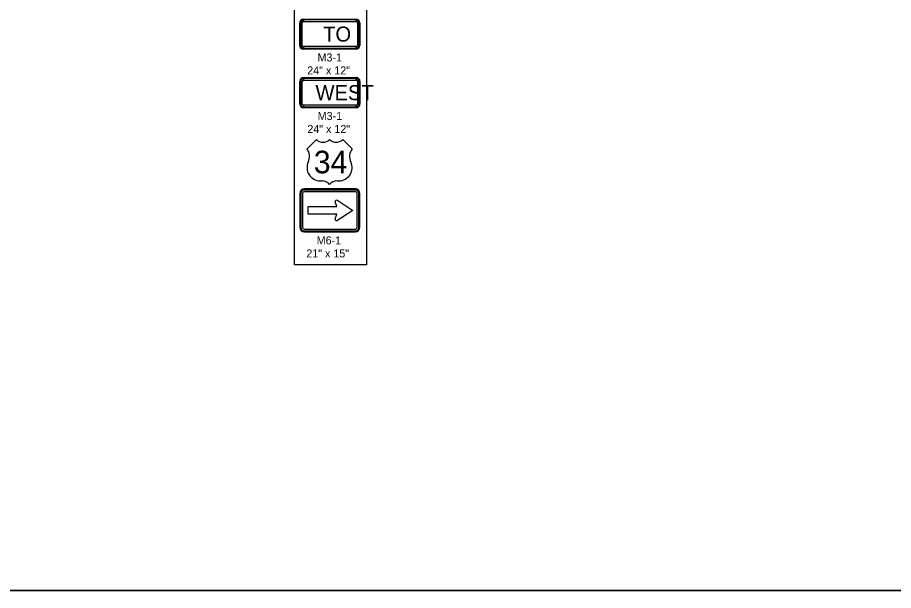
# Model space of a CAD drawing. Extents: x 10133 to 81668, y 6132 to 11018.
# Drawn here: x 11517 to 12392, y 7924 to 8497 of the extents above; entities that cross this region are included whole.
import ezdxf

# ---------------------------------------------------------------- set-up
doc = ezdxf.new("R2010")
doc.units = 0
for name, color, linetype in [('dsnTextFinalPlan', 7, 'Continuous'), ('Level 10', 7, 'Continuous'), ('Level 4', 7, 'Continuous'), ('Level 5', 7, 'Continuous'), ('SheetBorder', 7, 'Continuous'), ('SheetText', 7, 'Continuous')]:
    doc.layers.add(name, color=color, linetype=linetype)

msp = doc.modelspace()

# ---------------------------------------------------------------- linework, layer by layer
at = {"layer": 'dsnTextFinalPlan'}
msp.add_lwpolyline([(11793.9, 8561.72), (11865.97, 8561.72), (11865.97, 8249.49), (11793.9, 8249.49)], close=True, dxfattribs=at)
msp.add_lwpolyline([(11793.9, 8561.72), (11865.97, 8561.72), (11865.97, 8249.49), (11793.9, 8249.49)], close=True, dxfattribs=at)
at = {"layer": 'Level 10'}
for p, q in [((11799.19, 8468.76), (11799.19, 8491.3)), ((11800.13, 8491.3), (11801.69, 8491.3)), ((11802.95, 8495.06), (11855.56, 8495.06)), ((11802.95, 8492.56), (11802.95, 8494.12)), ((11855.56, 8494.12), (11855.56, 8492.56)), ((11856.81, 8491.3), (11858.38, 8491.3)), ((11859.32, 8491.3), (11859.32, 8468.76)), ((11801.69, 8468.76), (11800.13, 8468.76)), ((11802.95, 8465.94), (11802.95, 8467.5)), ((11855.56, 8465), (11802.95, 8465)), ((11855.56, 8467.5), (11855.56, 8465.94)), ((11858.38, 8468.76), (11856.81, 8468.76)), ((11803.05, 8436.52), (11855.66, 8436.52)), ((11799.29, 8410.21), (11799.29, 8432.76)), ((11800.23, 8432.76), (11801.8, 8432.76)), ((11803.05, 8434.01), (11803.05, 8435.58)), ((11855.66, 8435.58), (11855.66, 8434.01)), ((11856.92, 8432.76), (11858.48, 8432.76)), ((11859.42, 8432.76), (11859.42, 8410.21)), ((11801.8, 8410.21), (11800.23, 8410.21)), ((11858.48, 8410.21), (11856.92, 8410.21)), ((11803.05, 8407.39), (11803.05, 8408.96)), ((11855.66, 8406.45), (11803.05, 8406.45)), ((11855.66, 8408.96), (11855.66, 8407.39)), ((11854.79, 8325.33), (11803.83, 8325.33)), ((11854.79, 8324.18), (11803.83, 8324.18)), ((11854.79, 8322.47), (11803.83, 8322.47)), ((11799.25, 8320.75), (11799.25, 8286.96)), ((11800.39, 8320.75), (11800.39, 8286.96)), ((11802.11, 8320.75), (11802.11, 8286.96)), ((11856.51, 8286.96), (11856.51, 8320.75)), ((11858.23, 8286.96), (11858.23, 8320.75)), ((11859.37, 8286.96), (11859.37, 8320.75)), ((11803.83, 8285.24), (11854.79, 8285.24)), ((11803.83, 8283.53), (11854.79, 8283.53)), ((11803.83, 8282.38), (11854.79, 8282.38))]:
    msp.add_line(p, q, dxfattribs=at)
for points in [[(11800.13, 8491.3), (11800.13, 8468.76), (11801.69, 8468.76), (11801.69, 8491.3), (11800.13, 8491.3)], [(11855.56, 8494.12), (11802.95, 8494.12), (11802.95, 8492.56), (11855.56, 8492.56), (11855.56, 8494.12)], [(11858.38, 8468.76), (11858.38, 8491.3), (11856.81, 8491.3), (11856.81, 8468.76), (11858.38, 8468.76)], [(11802.95, 8465.94), (11855.56, 8465.94), (11855.56, 8467.5), (11802.95, 8467.5), (11802.95, 8465.94)], [(11800.23, 8432.76), (11800.23, 8410.21), (11801.8, 8410.21), (11801.8, 8432.76), (11800.23, 8432.76)], [(11855.66, 8435.58), (11803.05, 8435.58), (11803.05, 8434.01), (11855.66, 8434.01), (11855.66, 8435.58)], [(11858.48, 8410.21), (11858.48, 8432.76), (11856.92, 8432.76), (11856.92, 8410.21), (11858.48, 8410.21)], [(11803.05, 8407.39), (11855.66, 8407.39), (11855.66, 8408.96), (11803.05, 8408.96), (11803.05, 8407.39)]]:
    msp.add_lwpolyline(points, close=True, dxfattribs=at)
for points in [[(11837.23, 8313.67), (11852.22, 8303.86), (11837.23, 8294.07)], [(11834.76, 8295.4), (11836.13, 8299.98), (11807.6, 8299.98), (11807.6, 8307.73), (11836.13, 8307.73), (11834.73, 8312.31)]]:
    msp.add_lwpolyline(points, dxfattribs=at)
for centre, radius, start, end in [((11802.95, 8491.3), 3.76, 90, 180), ((11802.95, 8491.3), 2.82, 90.00021, 179.99985), ((11802.95, 8491.3), 1.25, 90.00021, 179.99985), ((11855.56, 8491.3), 3.76, 0, 90), ((11855.56, 8491.3), 2.82, 0, 90.00021), ((11855.56, 8491.3), 1.25, 0, 90.00021), ((11802.95, 8468.76), 3.76, 180, 270), ((11802.95, 8468.76), 2.82, 179.99985, 270.00006), ((11802.95, 8468.76), 1.25, 179.99985, 270.00006), ((11855.56, 8468.76), 2.82, 270.00006, 0.00027), ((11855.56, 8468.76), 1.25, 270.00006, 0.00027), ((11855.56, 8468.76), 3.76, 270, 359.99112), ((11803.05, 8432.76), 3.76, 90, 180), ((11855.66, 8432.76), 3.76, 0, 90), ((11803.05, 8432.76), 2.82, 90.00021, 179.99985), ((11803.05, 8432.76), 1.25, 90.00021, 179.99985), ((11855.66, 8432.76), 2.82, 0, 90.00021), ((11855.66, 8432.76), 1.25, 0, 90.00021), ((11803.05, 8410.21), 3.76, 180, 270), ((11803.05, 8410.21), 2.82, 179.99985, 270.00006), ((11803.05, 8410.21), 1.25, 179.99985, 270.00006), ((11855.66, 8410.21), 2.82, 270.00006, 0.00027), ((11855.66, 8410.21), 1.25, 270.00006, 0.00027), ((11855.66, 8410.21), 3.76, 270, 359.99112), ((11803.83, 8320.75), 4.58, 90, 180), ((11803.83, 8320.75), 3.44, 90, 180), ((11803.83, 8320.75), 1.72, 90, 180), ((11854.79, 8320.75), 4.58, 360, 90), ((11854.79, 8320.75), 3.44, 0, 90), ((11854.79, 8320.75), 1.72, 0, 90), ((11836.11, 8312.7), 1.43, 56.61094, 195.96908), ((11915.68, 8433.43), 143.16, 236.61094, 236.7714), ((11836.11, 8295.01), 1.4, 164.03092, 303.3104), ((11915.5, 8174.2), 143.16, 123.14303, 123.31039), ((11803.83, 8286.96), 4.58, 180, 270), ((11803.83, 8286.96), 3.44, 180, 270), ((11803.83, 8286.96), 1.72, 180, 270), ((11854.79, 8286.96), 4.58, 270, 0), ((11854.79, 8286.96), 3.44, 270, 360), ((11854.79, 8286.96), 1.72, 270, 0)]:
    msp.add_arc(centre, radius, start, end, dxfattribs=at)
at = {"layer": 'Level 4'}
for p, q in [((11815.89, 8374.68), (11806.51, 8365.31)), ((11815.89, 8374.68), (11806.51, 8365.31)), ((11851.51, 8365.31), (11842.14, 8374.68)), ((11851.51, 8365.31), (11842.14, 8374.68)), ((11819.64, 8333.43), (11821.51, 8333.43)), ((11819.64, 8333.43), (11821.51, 8333.43)), ((11836.51, 8333.43), (11838.39, 8333.43)), ((11836.51, 8333.43), (11838.39, 8333.43))]:
    msp.add_line(p, q, dxfattribs=at)
for centre, radius, start, end in [((11822.45, 8381.38), 9.38, 225.57291, 314.42721), ((11822.45, 8381.38), 9.38, 225.57291, 314.42721), ((11835.57, 8381.38), 9.38, 225.57291, 314.42721), ((11835.57, 8381.38), 9.38, 225.57291, 314.42721), ((11795.85, 8357.65), 13.13, 334.98952, 35.66288), ((11795.85, 8357.65), 13.13, 334.98952, 35.66288), ((11862.17, 8357.65), 13.13, 144.33724, 205.01003), ((11862.17, 8357.65), 13.13, 144.33724, 205.01003), ((11819.64, 8346.56), 13.13, 154.98967, 270.00006), ((11819.64, 8346.56), 13.13, 154.98967, 270.00006), ((11838.39, 8346.56), 13.13, 270.00006, 25.01045), ((11838.39, 8346.56), 13.13, 270.00006, 25.01045), ((11821.51, 8324.06), 9.38, 36.86989, 90.00021), ((11821.51, 8324.06), 9.38, 36.86989, 90.00021), ((11836.51, 8324.06), 9.38, 90.00021, 143.13001), ((11836.51, 8324.06), 9.38, 90.00021, 143.13001)]:
    msp.add_arc(centre, radius, start, end, dxfattribs=at)
at = {"layer": 'SheetBorder'}
msp.add_lwpolyline([(10132.52, 9944.02), (13267.53, 9944.02), (13267.53, 7924.02), (10132.52, 7924.02)], close=True, dxfattribs=at)
at = {"layer": 'SheetText'}
msp.add_lwpolyline([(10132.52, 9944.02), (10132.52, 7924.02), (13267.53, 7924.02), (13267.53, 9944.02)], close=True, dxfattribs=at)

# ---------------------------------------------------------------- texts
at = {"layer": 'Level 10'}
for s, p in [('TO', (11822.61, 8472.51)), ('WEST', (11815.03, 8413.97))]:
    msp.add_text(s, height=15.032, dxfattribs=at).set_placement(p)
at = {"layer": 'Level 4'}
msp.add_text('34', height=22.5, dxfattribs=at).set_placement((11813.31, 8340.93))
msp.add_text('34', height=22.5, dxfattribs=at).set_placement((11813.31, 8340.93))
at = {"layer": 'Level 5'}
for s, p in [('M3-1', (11817.07, 8452.71)), ('24" x 12"', (11806.74, 8439.71)), ('M3-1', (11817.18, 8394.16)), ('24" x 12"', (11806.84, 8381.16)), ('M6-1', (11816.17, 8269.87)), ('21" x 15"', (11805.84, 8256.87))]:
    msp.add_text(s, height=8, dxfattribs=at).set_placement(p)

doc.saveas('drawing.dxf')
